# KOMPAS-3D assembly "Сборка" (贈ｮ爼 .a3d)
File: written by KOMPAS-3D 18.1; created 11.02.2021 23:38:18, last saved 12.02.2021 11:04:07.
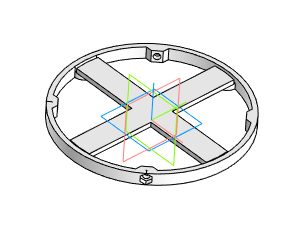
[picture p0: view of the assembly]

Document properties: Полное имя файла: C:\GoogleDrive\НИР\ИКИ\Компас\Сборка.a3d

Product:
- Part/product: Сборка
    Масса: 0.179629
  - Component [detail]: Деталь  | Масса: 0.160372; source file: Крестовина.m3d
  - Component [detail]: Деталь  | Материал: Полипропилен  ГОСТ 26996-86 (density 900 kg/m3); Масса: 0.0192571; source file: Распорное кольцо.m3d

Referenced files in C:\GoogleDrive\НИР\ИКИ\Компас\: Распорное кольцо.m3d, Крестовина.m3d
